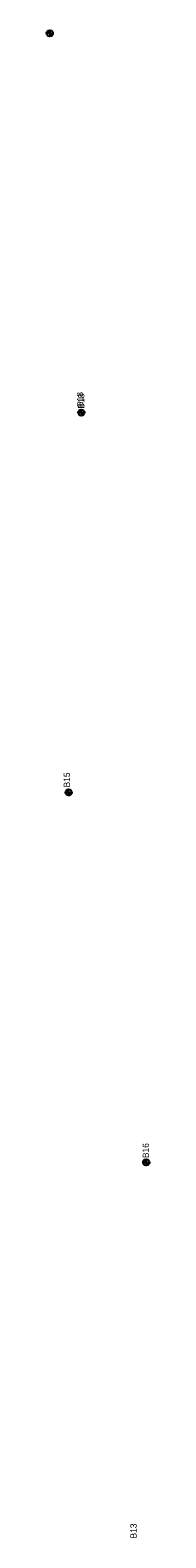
# Model space of a CAD drawing. Extents: x 327762 to 372792, y 127949 to 259367.
# Drawn here: x 361138 to 361301, y 135576 to 137973 of the extents above; entities that cross this region are included whole.
import ezdxf

# ---------------------------------------------------------------- set-up
doc = ezdxf.new("R2010")
doc.units = 0
for name, color, linetype in [('E_SOIL_BORE1 [KAPUR_CADDS_LEVELS]', 7, 'Continuous'), ('E_SOIL_BORE2 [KAPUR_CADDS_LEVELS]', 7, 'Continuous'), ('P_MARK', 7, 'Continuous')]:
    doc.layers.add(name, color=color, linetype=linetype)

msp = doc.modelspace()

# ---------------------------------------------------------------- linework, layer by layer
at = {"layer": 'P_MARK'}
for p, q in [((361143.1, 137973.3), (361143.1, 137963.3)), ((361138.1, 137968.3), (361148.1, 137968.3)), ((361193.2, 137370.2), (361193.2, 137360.2)), ((361188.2, 137365.2), (361198.2, 137365.2)), ((361168.1, 136761.5), (361178.1, 136761.5)), ((361173.1, 136766.5), (361173.1, 136756.5)), ((361291.4, 136173.3), (361301.4, 136173.3)), ((361296.4, 136178.3), (361296.4, 136168.3))]:
    msp.add_line(p, q, dxfattribs=at)
for centre in [(361143.1, 137968.3), (361193.2, 137365.2), (361173.1, 136761.5), (361296.4, 136173.3)]:
    msp.add_circle(centre, 5, dxfattribs=at)
for centre, radius, start, end in [((361143.1, 137968.3), 4.5, 89.9869, 179.9869), ((361143.1, 137968.3), 4, 89.9869, 179.9869), ((361143.1, 137968.3), 3.5, 89.9869, 179.9869), ((361143.1, 137968.3), 3, 89.9869, 179.9869), ((361143.1, 137968.3), 2.5, 89.9869, 179.9869), ((361143.1, 137968.3), 2, 89.9869, 179.9869), ((361143.1, 137968.3), 1.5, 89.9869, 179.9869), ((361143.1, 137968.3), 1, 89.9869, 179.9869), ((361143.1, 137968.3), 0.5, 89.9869, 179.9869), ((361143.1, 137968.3), 4.5, 269.9869, 359.9869), ((361143.1, 137968.3), 4, 269.9869, 359.9869), ((361143.1, 137968.3), 3.5, 269.9869, 359.9869), ((361143.1, 137968.3), 3, 269.9869, 359.9869), ((361143.1, 137968.3), 2.5, 269.9869, 359.9869), ((361143.1, 137968.3), 2, 269.9869, 359.9869), ((361143.1, 137968.3), 1.5, 269.9869, 359.9869), ((361143.1, 137968.3), 1, 269.9869, 359.9869), ((361143.1, 137968.3), 0.5, 269.9869, 359.9869), ((361193.2, 137365.2), 4.5, 89.9869, 179.9869), ((361193.2, 137365.2), 4, 89.9869, 179.9869), ((361193.2, 137365.2), 3.5, 89.9869, 179.9869), ((361193.2, 137365.2), 3, 89.9869, 179.9869), ((361193.2, 137365.2), 2.5, 89.9869, 179.9869), ((361193.2, 137365.2), 2, 89.9869, 179.9869), ((361193.2, 137365.2), 1.5, 89.9869, 179.9869), ((361193.2, 137365.2), 1, 89.9869, 179.9869), ((361193.2, 137365.2), 0.5, 89.9869, 179.9869), ((361193.2, 137365.2), 4.5, 269.9869, 359.9869), ((361193.2, 137365.2), 4, 269.9869, 359.9869), ((361193.2, 137365.2), 3.5, 269.9869, 359.9869), ((361193.2, 137365.2), 3, 269.9869, 359.9869), ((361193.2, 137365.2), 2.5, 269.9869, 359.9869), ((361193.2, 137365.2), 2, 269.9869, 359.9869), ((361193.2, 137365.2), 1.5, 269.9869, 359.9869), ((361193.2, 137365.2), 1, 269.9869, 359.9869), ((361193.2, 137365.2), 0.5, 269.9869, 359.9869), ((361173.1, 136761.5), 4.5, 89.9869, 179.9869), ((361173.1, 136761.5), 4, 89.9869, 179.9869), ((361173.1, 136761.5), 3.5, 89.9869, 179.9869), ((361173.1, 136761.5), 3, 89.9869, 179.9869), ((361173.1, 136761.5), 2.5, 89.9869, 179.9869), ((361173.1, 136761.5), 2, 89.9869, 179.9869), ((361173.1, 136761.5), 1.5, 89.9869, 179.9869), ((361173.1, 136761.5), 1, 89.9869, 179.9869), ((361173.1, 136761.5), 0.5, 89.9869, 179.9869), ((361173.1, 136761.5), 4.5, 269.9869, 359.9869), ((361173.1, 136761.5), 4, 269.9869, 359.9869), ((361173.1, 136761.5), 3.5, 269.9869, 359.9869), ((361173.1, 136761.5), 3, 269.9869, 359.9869), ((361173.1, 136761.5), 2.5, 269.9869, 359.9869), ((361173.1, 136761.5), 2, 269.9869, 359.9869), ((361173.1, 136761.5), 1.5, 269.9869, 359.9869), ((361173.1, 136761.5), 1, 269.9869, 359.9869), ((361173.1, 136761.5), 0.5, 269.9869, 359.9869), ((361296.4, 136173.3), 4.5, 89.9869, 179.9869), ((361296.4, 136173.3), 4, 89.9869, 179.9869), ((361296.4, 136173.3), 3.5, 89.9869, 179.9869), ((361296.4, 136173.3), 3, 89.9869, 179.9869), ((361296.4, 136173.3), 2.5, 89.9869, 179.9869), ((361296.4, 136173.3), 2, 89.9869, 179.9869), ((361296.4, 136173.3), 1.5, 89.9869, 179.9869), ((361296.4, 136173.3), 1, 89.9869, 179.9869), ((361296.4, 136173.3), 0.5, 89.9869, 179.9869), ((361296.4, 136173.3), 4.5, 269.9869, 359.9869), ((361296.4, 136173.3), 4, 269.9869, 359.9869), ((361296.4, 136173.3), 3.5, 269.9869, 359.9869), ((361296.4, 136173.3), 3, 269.9869, 359.9869), ((361296.4, 136173.3), 2.5, 269.9869, 359.9869), ((361296.4, 136173.3), 2, 269.9869, 359.9869), ((361296.4, 136173.3), 1.5, 269.9869, 359.9869), ((361296.4, 136173.3), 1, 269.9869, 359.9869), ((361296.4, 136173.3), 0.5, 269.9869, 359.9869)]:
    msp.add_arc(centre, radius, start, end, dxfattribs=at)

# ---------------------------------------------------------------- texts
at = {"layer": 'E_SOIL_BORE1 [KAPUR_CADDS_LEVELS]'}
for s, p in [('B18', (361196.2, 137374.2)), ('B13', (361281.2, 135575.3))]:
    msp.add_text(s, height=10, rotation=89.9869, dxfattribs=at).set_placement(p)
at = {"layer": 'E_SOIL_BORE2 [KAPUR_CADDS_LEVELS]'}
for s, p in [('B18', (361198.1, 137371.6)), ('B15', (361175.1, 136769.4)), ('B16', (361300.6, 136180.1))]:
    msp.add_text(s, height=10, rotation=89.9869, dxfattribs=at).set_placement(p)

doc.saveas('drawing.dxf')
